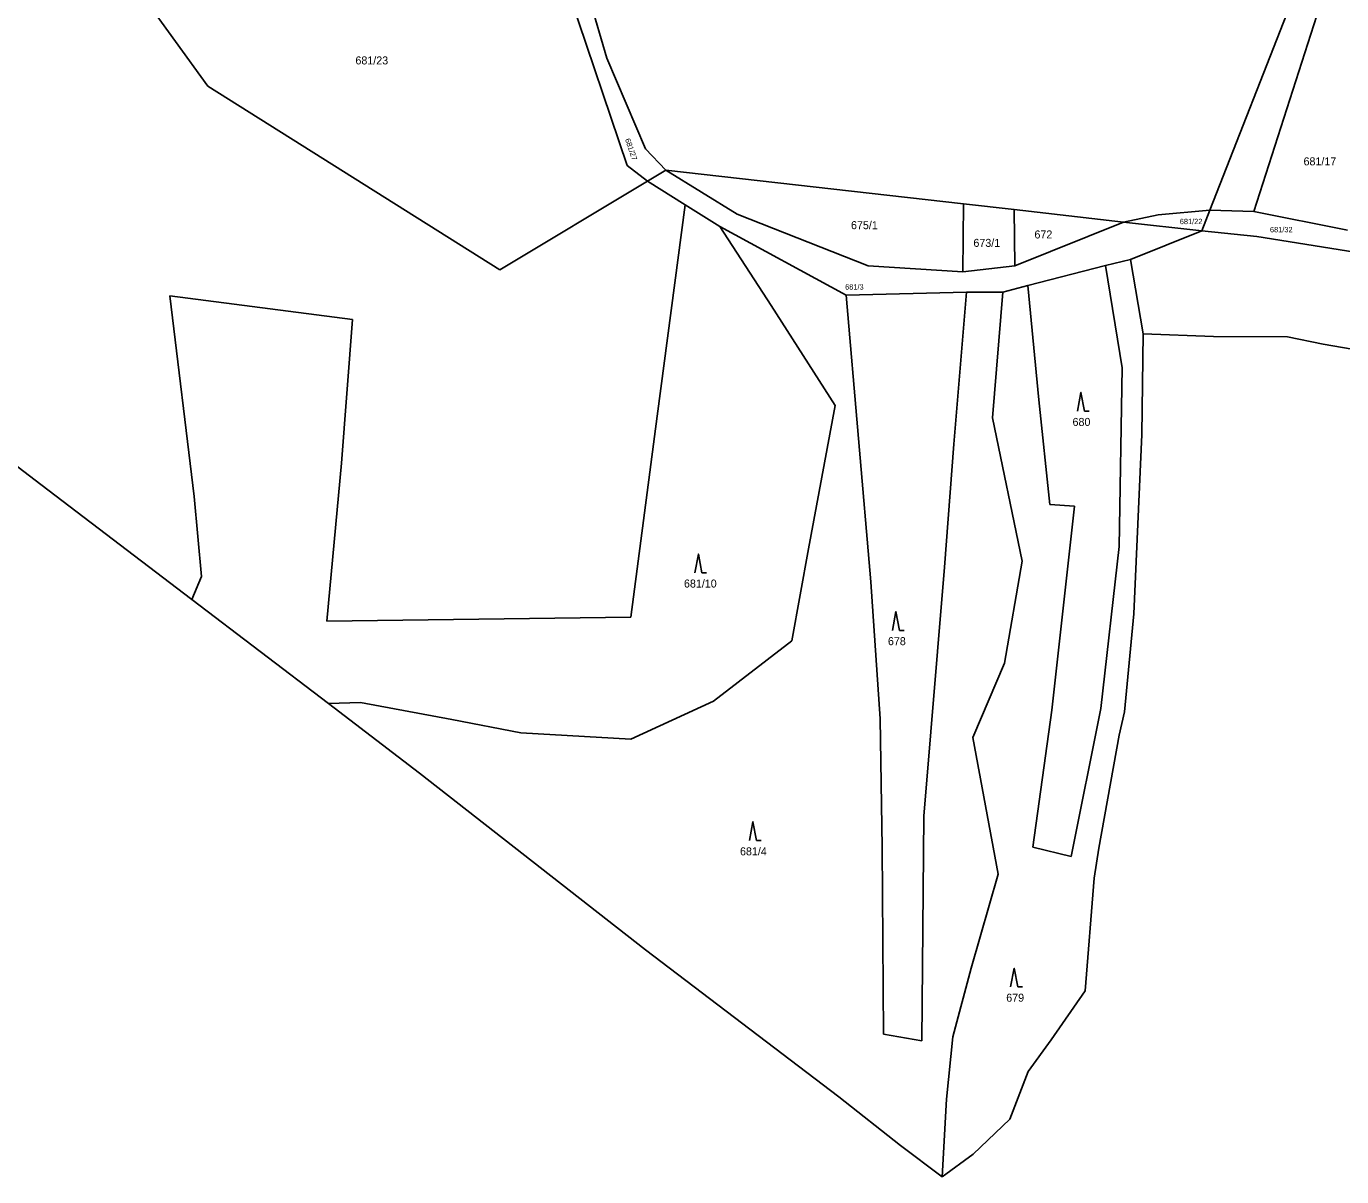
# Model space of a CAD drawing. Extents: x -701211 to -698780, y -1014269 to -1012378.
# Drawn here: x -700355.1 to -700075.5, y -1014269.2 to -1014024.8 of the extents above; entities that cross this region are included whole.
import ezdxf
from ezdxf.enums import TextEntityAlignment as Align

# ---------------------------------------------------------------- set-up
doc = ezdxf.new("R2010")
doc.units = 0
doc.header["$LTSCALE"] = 0.68
doc.layers.add('1', color=7, linetype='Continuous', lineweight=25)
doc.layers.add('3', color=7, linetype='Continuous', lineweight=25)
doc.layers.add('2', color=7, linetype='Continuous')

msp = doc.modelspace()

# ---------------------------------------------------------------- linework, layer by layer
at = {"layer": '1'}
for p, q in [((-700346.3, -1013996.29), (-700316.48, -1014037.51)), ((-700103.57, -1014063.88), (-700081.91, -1014008.58)), ((-700227.36, -1014054.33), (-700239.68, -1014017.84)), ((-700094.24, -1014064.11), (-700078.87, -1014016.26)), ((-700235.33, -1014019.18), (-700231.73, -1014031.58)), ((-700231.73, -1014031.58), (-700223.48, -1014050.79)), ((-700316.48, -1014037.51), (-700254.44, -1014076.56)), ((-700223.48, -1014050.79), (-700219.17, -1014055.35)), ((-700223.03, -1014057.67), (-700227.36, -1014054.33)), ((-700223.03, -1014057.67), (-700219.17, -1014055.35)), ((-700155.88, -1014062.52), (-700219.17, -1014055.35)), ((-700204.01, -1014064.74), (-700219.17, -1014055.35)), ((-700254.44, -1014076.56), (-700223.03, -1014057.67)), ((-700223.03, -1014057.67), (-700215.07, -1014062.75)), ((-700215.07, -1014062.75), (-700220.97, -1014107.65)), ((-700207.67, -1014067.34), (-700215.07, -1014062.75)), ((-700156.02, -1014076.95), (-700155.88, -1014062.52)), ((-700155.88, -1014062.52), (-700145.14, -1014063.74)), ((-700204.01, -1014064.74), (-700176.2, -1014075.69)), ((-700144.99, -1014075.69), (-700145.14, -1014063.74)), ((-700145.14, -1014063.74), (-700121.88, -1014066.38)), ((-700114.54, -1014064.84), (-700121.88, -1014066.38)), ((-700103.57, -1014063.88), (-700114.54, -1014064.84)), ((-700105.28, -1014068.26), (-700103.57, -1014063.88)), ((-700094.24, -1014064.11), (-700103.57, -1014063.88)), ((-700094.24, -1014064.11), (-700074.28, -1014068.1)), ((-700180.83, -1014081.9), (-700207.67, -1014067.34)), ((-700207.67, -1014067.34), (-700196.81, -1014084.12)), ((-700144.99, -1014075.69), (-700121.88, -1014066.38)), ((-700121.88, -1014066.38), (-700105.28, -1014068.26)), ((-700120.46, -1014074.36), (-700105.28, -1014068.26)), ((-700105.28, -1014068.26), (-700093.55, -1014069.48)), ((-700093.55, -1014069.48), (-700067.76, -1014073.58)), ((-700176.2, -1014075.69), (-700156.02, -1014076.95)), ((-700156.02, -1014076.95), (-700144.99, -1014075.69)), ((-700142.25, -1014079.83), (-700125.76, -1014075.61)), ((-700125.76, -1014075.61), (-700120.46, -1014074.36)), ((-700122.17, -1014097.33), (-700125.76, -1014075.61)), ((-700120.46, -1014074.36), (-700117.76, -1014090.15)), ((-700324.57, -1014082.09), (-700319.36, -1014124.71)), ((-700285.73, -1014087.11), (-700324.57, -1014082.09)), ((-700180.83, -1014081.9), (-700155.25, -1014081.25)), ((-700175.62, -1014142.82), (-700180.83, -1014081.9)), ((-700155.25, -1014081.25), (-700157.99, -1014113.6)), ((-700147.54, -1014081.27), (-700155.25, -1014081.25)), ((-700149.78, -1014108), (-700147.54, -1014081.27)), ((-700147.54, -1014081.27), (-700142.25, -1014079.83)), ((-700142.25, -1014079.83), (-700139.92, -1014104.15)), ((-700402.11, -1014083.8), (-700351.96, -1014122.18)), ((-700196.81, -1014084.12), (-700183.18, -1014105.38)), ((-700288.06, -1014117.62), (-700285.73, -1014087.11)), ((-700117.76, -1014090.15), (-700118.04, -1014111.54)), ((-700102.76, -1014090.71), (-700117.76, -1014090.15)), ((-700087.09, -1014090.8), (-700102.76, -1014090.71)), ((-700079.49, -1014092.3), (-700087.09, -1014090.8)), ((-700058.11, -1014096.06), (-700079.49, -1014092.3)), ((-700122.8, -1014135.36), (-700122.17, -1014097.33)), ((-700139.92, -1014104.15), (-700137.58, -1014126.4)), ((-700183.18, -1014105.38), (-700188.88, -1014135.85)), ((-700220.97, -1014107.65), (-700226.61, -1014150.37)), ((-700143.41, -1014138.42), (-700149.78, -1014108)), ((-700118.04, -1014111.54), (-700119.73, -1014149.63)), ((-700157.99, -1014113.6), (-700159.93, -1014139.69)), ((-700291.2, -1014151.18), (-700288.06, -1014117.62)), ((-700351.96, -1014122.18), (-700319.9, -1014146.58)), ((-700319.36, -1014124.71), (-700317.84, -1014141.67)), ((-700137.58, -1014126.4), (-700132.29, -1014126.76)), ((-700132.29, -1014126.76), (-700137.14, -1014170.09)), ((-700126.74, -1014169.72), (-700122.8, -1014135.36)), ((-700188.88, -1014135.85), (-700192.36, -1014155.39)), ((-700159.93, -1014139.69), (-700164.31, -1014192.64)), ((-700147.18, -1014160.14), (-700143.41, -1014138.42)), ((-700317.84, -1014141.67), (-700319.9, -1014146.58)), ((-700173.65, -1014171.98), (-700175.62, -1014142.82)), ((-700319.9, -1014146.58), (-700290.87, -1014168.67)), ((-700226.61, -1014150.37), (-700291.2, -1014151.18)), ((-700119.73, -1014149.63), (-700121.69, -1014170.46)), ((-700192.36, -1014155.39), (-700209.04, -1014168.22)), ((-700153.9, -1014175.93), (-700147.18, -1014160.14)), ((-700284.03, -1014168.49), (-700290.87, -1014168.67)), ((-700290.87, -1014168.67), (-700271.54, -1014183.5)), ((-700264.65, -1014172.08), (-700284.03, -1014168.49)), ((-700209.04, -1014168.22), (-700226.62, -1014176.29)), ((-700137.14, -1014170.09), (-700141.18, -1014199.24)), ((-700133.02, -1014201.22), (-700126.74, -1014169.72)), ((-700121.69, -1014170.46), (-700122.82, -1014175.43)), ((-700249.94, -1014174.95), (-700264.65, -1014172.08)), ((-700173.2, -1014199.26), (-700173.65, -1014171.98)), ((-700226.62, -1014176.29), (-700249.94, -1014174.95)), ((-700148.52, -1014204.92), (-700153.9, -1014175.93)), ((-700122.82, -1014175.43), (-700127.13, -1014199.45)), ((-700271.54, -1014183.5), (-700223.49, -1014221)), ((-700164.31, -1014192.64), (-700164.78, -1014240.36)), ((-700172.94, -1014238.92), (-700173.2, -1014199.26)), ((-700141.18, -1014199.24), (-700133.02, -1014201.22)), ((-700127.13, -1014199.45), (-700128.16, -1014205.83)), ((-700154.27, -1014224.93), (-700148.52, -1014204.92)), ((-700128.16, -1014205.83), (-700130.04, -1014229.75)), ((-700223.49, -1014221), (-700182.37, -1014252.26)), ((-700158.16, -1014239.49), (-700154.27, -1014224.93)), ((-700130.04, -1014229.75), (-700137.26, -1014240.16)), ((-700164.78, -1014240.36), (-700172.94, -1014238.92)), ((-700159.5, -1014252.77), (-700158.16, -1014239.49)), ((-700137.26, -1014240.16), (-700142.14, -1014246.92)), ((-700142.14, -1014246.92), (-700146.07, -1014257.05)), ((-700182.37, -1014252.26), (-700169.33, -1014262.58)), ((-700160.42, -1014269.24), (-700159.5, -1014252.77)), ((-700146.07, -1014257.05), (-700153.86, -1014264.46)), ((-700169.33, -1014262.58), (-700160.42, -1014269.24)), ((-700153.86, -1014264.46), (-700160.42, -1014269.24))]:
    msp.add_line(p, q, dxfattribs=at)
at = {"layer": '3'}
for p, q in [((-700130.22, -1014106.58), (-700129.224, -1014106.58)), ((-700211.49, -1014140.92), (-700210.494, -1014140.92)), ((-700169.51, -1014153.17), (-700168.514, -1014153.17)), ((-700199.9, -1014197.83), (-700198.904, -1014197.83)), ((-700144.39, -1014228.93), (-700143.394, -1014228.93))]:
    msp.add_line(p, q, dxfattribs=at)
for points in [[(-700130.22, -1014106.58), (-700130.97, -1014102.58), (-700131.72, -1014106.58)], [(-700211.49, -1014140.92), (-700212.24, -1014136.92), (-700212.99, -1014140.92)], [(-700169.51, -1014153.17), (-700170.26, -1014149.17), (-700171.01, -1014153.17)], [(-700199.9, -1014197.83), (-700200.65, -1014193.83), (-700201.4, -1014197.83)], [(-700144.39, -1014228.93), (-700145.14, -1014224.93), (-700145.89, -1014228.93)]]:
    msp.add_lwpolyline(points, dxfattribs=at)

# ---------------------------------------------------------------- texts
at = {"layer": '2'}
for s, p in [('681/23', (-700285.12, -1014032.885)), ('680', (-700132.74, -1014109.705)), ('681/10', (-700215.31, -1014144.045)), ('678', (-700171.97, -1014156.295)), ('681/4', (-700203.4, -1014200.955)), ('679', (-700146.83, -1014232.055))]:
    msp.add_text(s, height=1.7, dxfattribs=at).set_placement(p)
msp.add_text('681/27', height=1.14, rotation=289, dxfattribs=at).set_placement((-700227.0667, -1014051.1064), align=Align.CENTER)
for s, height, p in [('681/17', 1.7, (-700080.18, -1014054.335)), ('675/1', 1.7, (-700176.97, -1014067.895)), ('672', 1.7, (-700138.939, -1014069.865)), ('681/22', 1.14, (-700107.549, -1014066.825)), ('681/32', 1.14, (-700088.389, -1014068.555)), ('673/1', 1.7, (-700150.96, -1014071.655)), ('681/3', 1.14, (-700179.099, -1014080.735))]:
    msp.add_text(s, height=height, dxfattribs=at).set_placement(p, align=Align.CENTER)

doc.saveas('drawing.dxf')
